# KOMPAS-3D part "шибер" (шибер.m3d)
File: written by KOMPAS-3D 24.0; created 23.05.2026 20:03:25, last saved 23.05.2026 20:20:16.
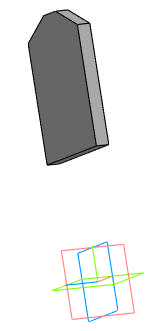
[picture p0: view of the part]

Document properties: Автор: R2D2; Полное имя файла: E:\Работа\Зайцев\GVKR1331M-1W-Fb-2P Задвижка шиберная с выдвижным штоком DN.ru Ду50-300 Ру16-10-6 с пневмоприводом\исходные материалы\DN65\шибер.m3d

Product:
- Part/product: шибер
    Масса: 0.645292
    Раздел спецификации: Прочие изделия
    Примечание: D040-08800

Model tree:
1. Эскиз:5  (with: Ребро.Элемент выдавливания:15, Ребро.Элемент выдавливания:2, Ребро.Скругление:10, Ребро.Элемент выдавливания:1)
2. Элемент выдавливания:6
     Расстояние 1 = 10

Referenced files in E:\Работа\Зайцев\GVKR1331M-1W-Fb-2P Задвижка шиберная с выдвижным штоком DN.ru Ду50-300 Ру16-10-6 с пневмоприводом\исходные материалы\DN65\: GVKR1331M-1W-Fb-2P Задвижка шиберная с выдвижным штоком DN.ru Ду65 Ру16.a3d
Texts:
  Затвор дисковый DN.ru Ду Ру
